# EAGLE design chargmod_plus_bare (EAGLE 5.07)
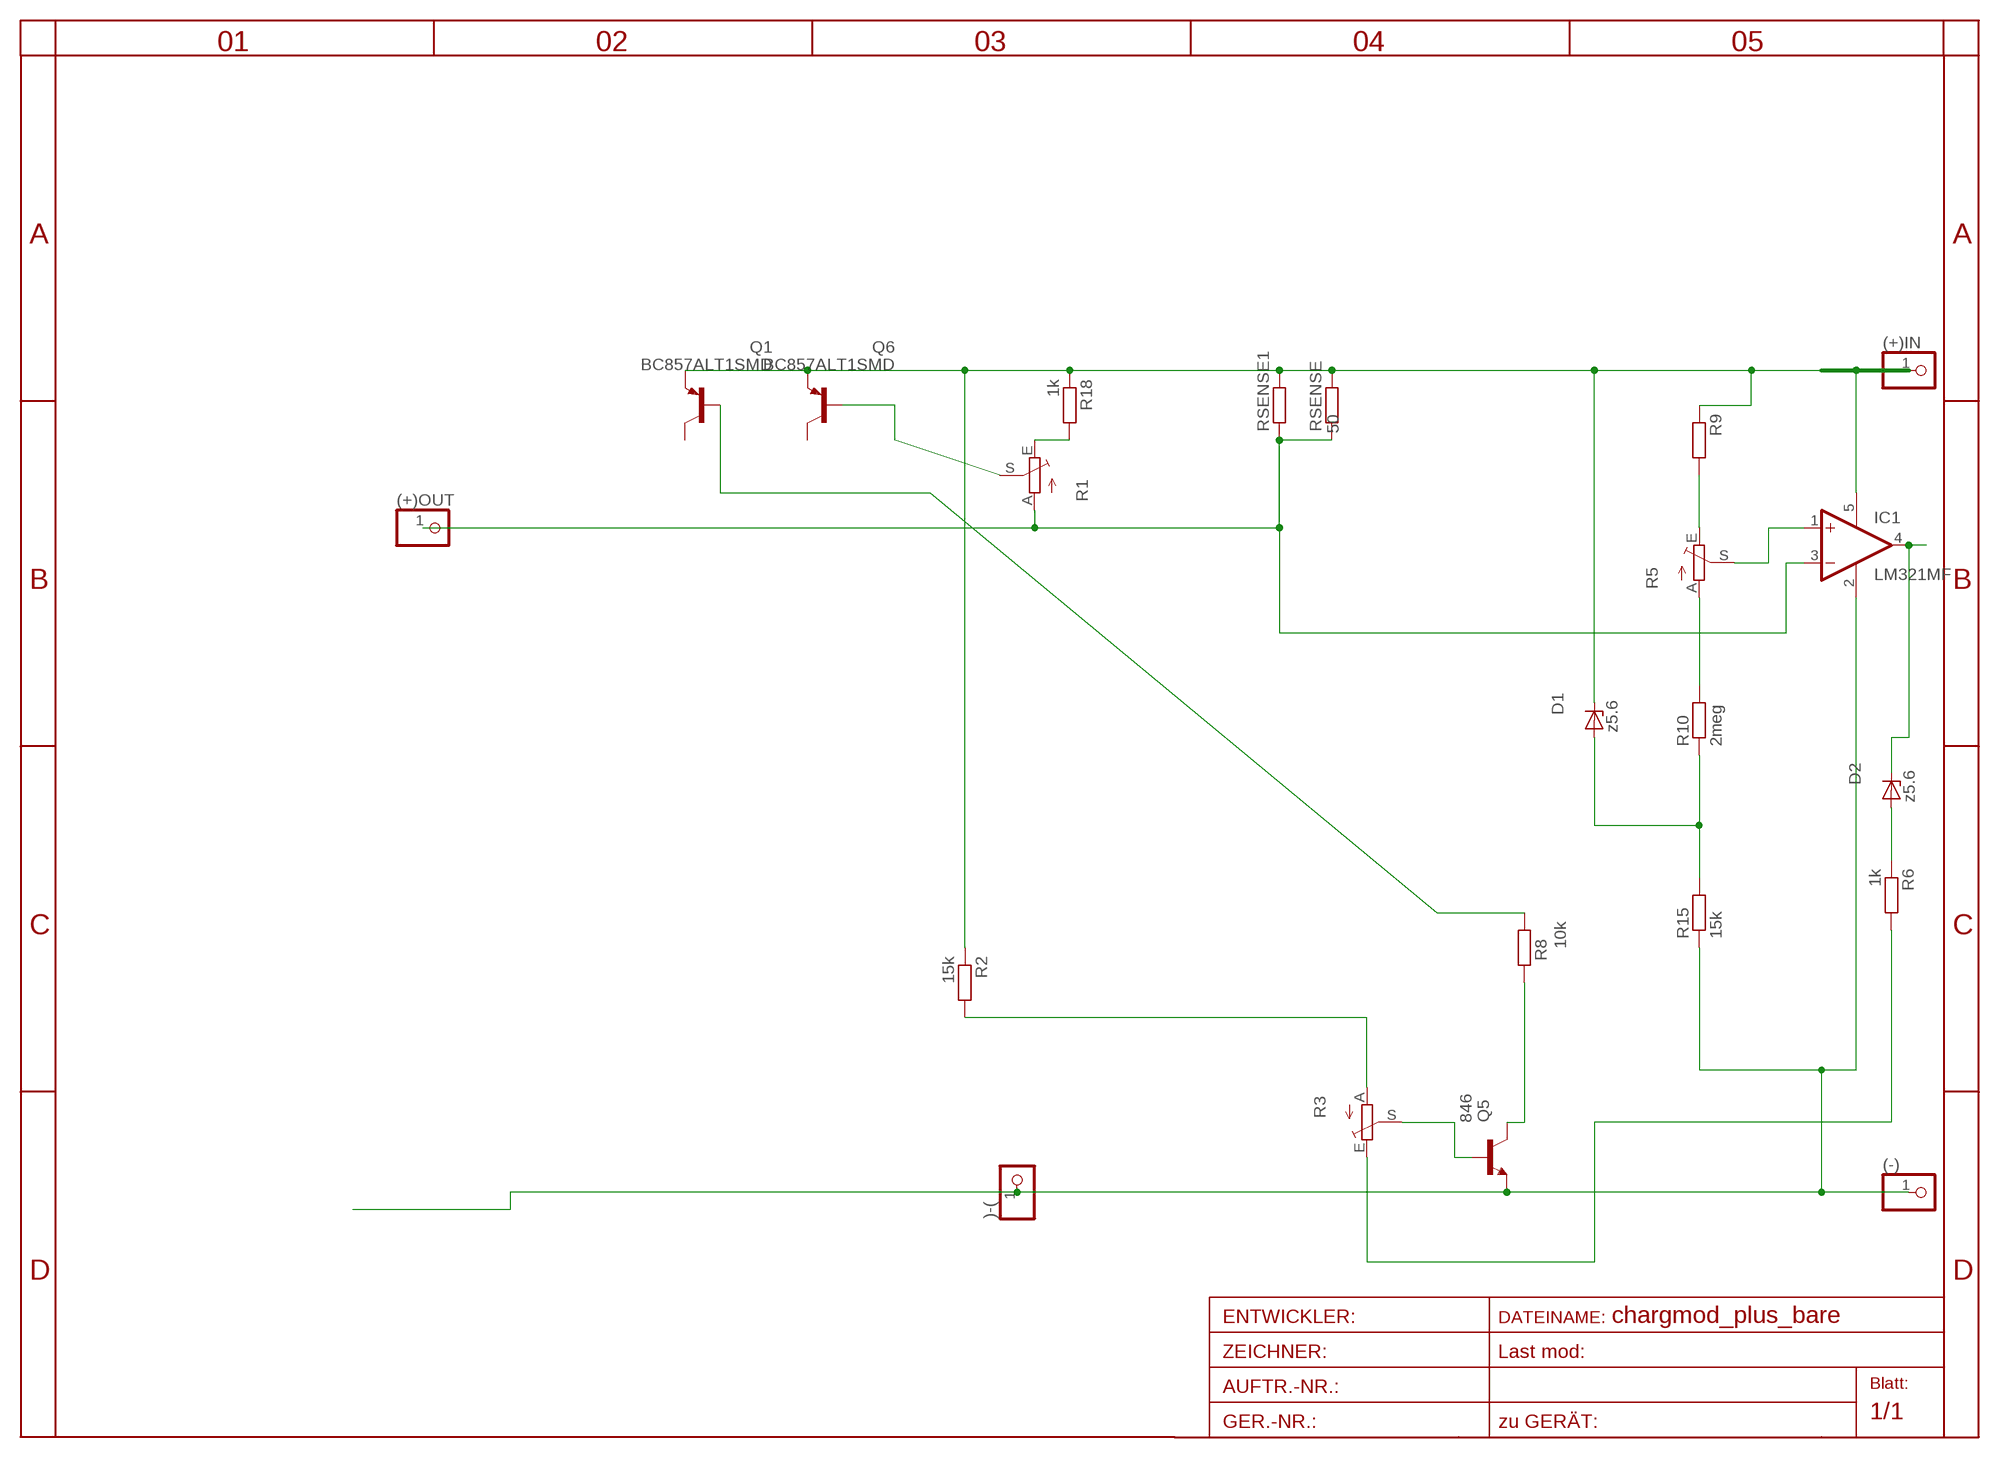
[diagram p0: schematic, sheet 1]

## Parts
(+)IN  PINHD-1X11MM6  [1X1MM8]
(+)OUT  PINHD-1X11MM6  [1X1MM8]
(-)  PINHD-1X11MM6  [1X1MM8]
)-(  PINHD-1X11MM6  [1X1MM8]
D1  z5.6  ZENER-DIODESOD80C  [SOD80C]
D2  z5.6  ZENER-DIODESOD80C  [SOD80C]
IC1  LM321MF  [SOT23-5]
Q1  BC857ALT1SMD  [SOT23-BEC]
Q5  846  BC846BSMD  [SOT23]
Q6  BC857ALT1SMD  [SOT23-BEC]
R1  TRIM_EU-S64W  [S64W]
R2  15k  R-EU_R0805  [R0805]
R3  TRIM_EU-S64W  [S64W]
R5  TRIM_EU-S64W  [S64W]
R6  1k  R-EU_R1206  [R1206]
R8  10k  R-EU_R0805  [R0805]
R9  50  R-EU_R0805  [R0805]
R10  2meg  R-EU_R0805  [R0805]
R15  15k  R-EU_R0805  [R0805]
R18  1k  R-EU_R1206  [R1206]
RSENSE  R-EU_0207/10  [0207/10]
RSENSE1  R-EU_0207/10  [0207/10]

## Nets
N$2: Q5.1(B) R3.S
N$3: R3.E R6.2
N$4: R2.2 R3.A
N$6: R5.A R10.2
N$7: Q1.B R8.1
N$9: (+)OUT.1 IC1.3(-IN) R1.A RSENSE1.1 RSENSE.1
N$13: D2.C IC1.4(OUT)
N$16: IC1.1(+IN) R5.S
N$17: Q6.B R1.S
N$19: D1.A R10.1 R15.2
N$20: Q5.3(C) R8.2
N$21: R5.E R9.2
N$22: R1.E R18.2
N$23: D2.A R6.1
V+IN: (+)IN.1 D1.C IC1.5(V+) Q1.E Q6.E R2.1 R9.1 R18.1 RSENSE1.2 RSENSE.2
VSS: (-).1 )-(.1 IC1.2(V-) Q5.2(E) R15.1
Unconnected: Q1.C Q6.C

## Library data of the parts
(+)IN (+)OUT (-) )-( = pinhead:PINHD-1X1: PIN HEADER
D1 D2 = diode-1:ZENER-DIODE: Z-Diode
IC1 = linear:LM321?*: Low Power Single Op Amp Source: http://cache.national.com/ds/LM/LM321.pdf
Q1 Q6 = transistor-pnp:BC857*: PNP Transistror
Q5 = transistor-npn:BC846*: NPN Transistor
R1 R3 R5 = pot:TRIM_EU-: POTENTIOMETER
R2 R6 R8-R10 R15 R18 RSENSE RSENSE1 = rcl:R-EU_: RESISTOR, European symbol

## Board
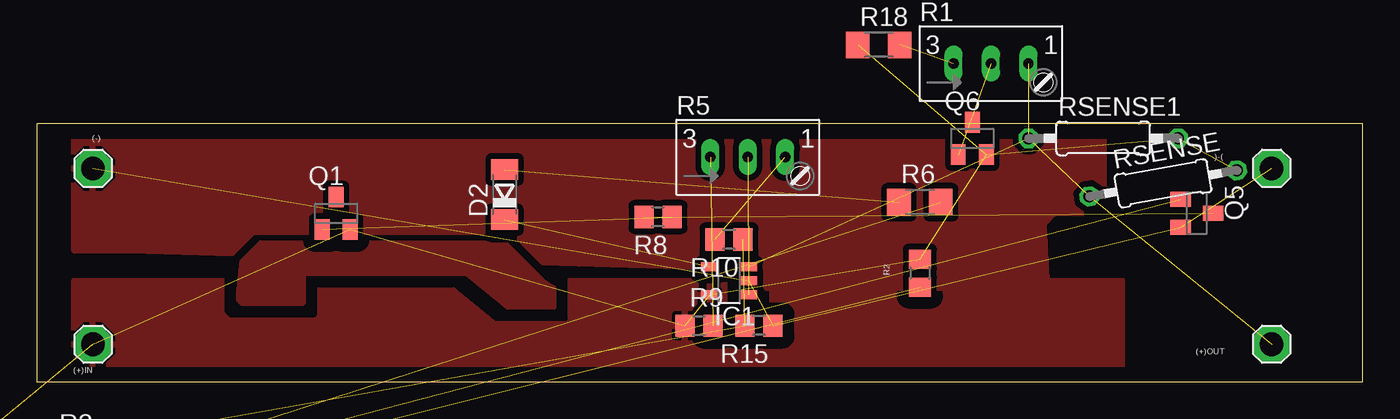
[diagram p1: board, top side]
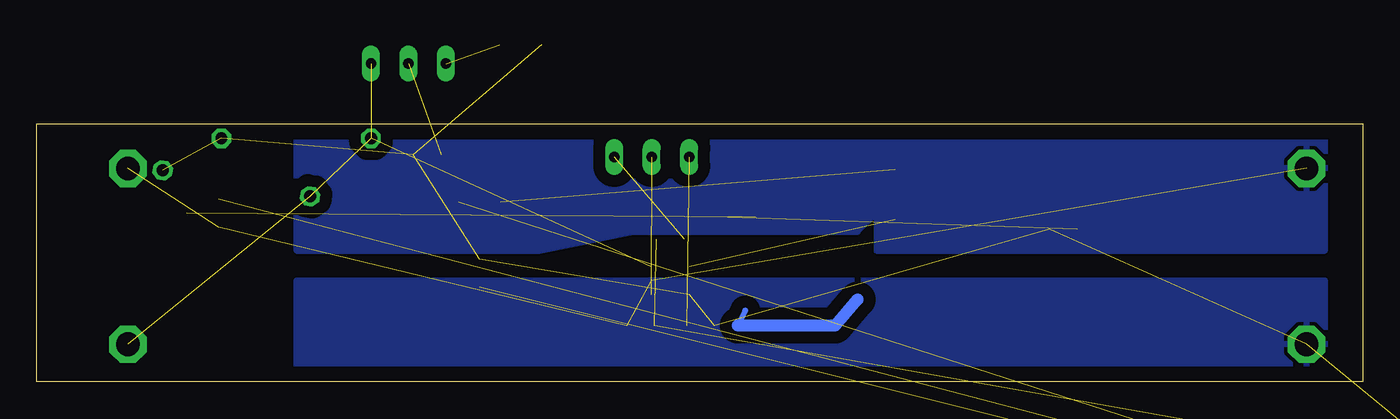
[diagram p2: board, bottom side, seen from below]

Size 90 x 17.5 mm. Coordinates in mm from the lower left corner, seen from the top.
Outline: 0,0 90,0 90,17.5 0,17.5 0,0
Copper layers (1*16): Top 0.035mm / dielectric 1.5mm / Bottom 0.035mm
Design rules "default *": minimum track width 10mil, minimum drill 14mil, track to track 8mil, track to pad 8mil, pad to pad 8mil, via to via 8mil, smd to smd 8mil, copper to edge 40mil, drill to drill 8mil, minimum pad ring 10mil, minimum via ring 8mil, stop-mask expansion 4mil, vias tented up to drill 0mil, thermal gap 10mil

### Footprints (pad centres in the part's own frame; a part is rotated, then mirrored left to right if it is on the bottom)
1X1MM8 = drill 1.6 pad 2.54 octagon: 1 0,0
SOD80C = smd 1.4 x 1.8: A 1.7,0; C -1.7,0
SOT23-5 = smd 0.6 x 1.2: 1 -0.95,-1.306; 2 0,-1.306; 3 0.95,-1.306; 4 0.95,1.306; 5 -0.95,1.306
SOT23-BEC = smd 1 x 1.4: B -0.95,-1.1; C 0,1.1; E 0.95,-1.1
SOT23 = smd 1 x 1.4: 1 -0.95,-1.1; 2 0.95,-1.1; 3 0,1.1
S64W = drill 0.7 long: A 2.54,1.27; E -2.54,1.27; S 0,1.27
R0805 = smd 1.3 x 1.5: 1 -0.95,0; 2 0.95,0
R1206 = smd 1.6 x 1.803: 1 -1.422,0; 2 1.422,0
0207/10 = drill 0.813 octagon: 1 -5.08,0; 2 5.08,0

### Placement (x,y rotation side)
(+)IN  3.81,2.54 0 top
(+)OUT  83.82,2.54 0 top
(-)  3.81,14.48 0 top
)-(  83.82,14.48 0 top
D1  not placed on the board
D2  31.75,12.7 90 top
IC1  46.99,6.86 90 top
Q1  20.32,11.43 0 top
Q5  78.74,11.43 270 top
Q6  63.5,16.51 0 top
R1  not placed on the board
R2  59.94,7.37 270 top
R3  not placed on the board
R5  48.26,13.97 0 top
R6  59.94,12.19 0 top
R8  42.16,11.18 180 top
R9  44.96,3.81 0 top
R10  46.99,9.65 180 top
R15  49.02,3.81 180 top
R18  not placed on the board
RSENSE  76.45,13.46 10 top
RSENSE1  72.39,16.51 0 top

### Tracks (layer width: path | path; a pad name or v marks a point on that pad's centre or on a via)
N$2  (1 unrouted)
N$3  (1 unrouted)
N$4  (1 unrouted)
N$6  (1 unrouted)
N$7  (1 unrouted)
N$9  (4 unrouted)
N$13  (1 unrouted)
N$16  (1 unrouted)
N$17  (1 unrouted)
N$19  (2 unrouted)
N$20  (1 unrouted)
N$21  (1 unrouted)
N$22  (1 unrouted)
N$23  (1 unrouted)
V+IN  (9 unrouted)
  pour Top (isolate 0.813, rank 5): 2.54,6.86 73.66,6.86 73.66,0.51 2.54,0.51
  pour Top: 73.66,5.59 73.66,3.05 69.85,3.05 69.85,4.32 71.12,5.59
  pour Bottom (isolate 0.813, rank 5): 2.54,6.86 72.39,6.86 72.39,0.51 2.54,0.51
VDD
  Bottom 0.406: 42.42,3.81 41.91,4.83
  Bottom 0.813: 42.42,3.81 35.81,3.81 34.29,5.59
  pour Top (isolate 0.813): 13.97,8.13 15.24,9.4 31.75,9.4 34.29,6.86 35.05,6.35 35.05,5.08 32,5.08 29.21,7.37 18.03,7.37 18.03,5.33 13.97,5.33 13.72,5.59
VSS  (4 unrouted)
  pour Top (isolate 0.406, rank 5): 6.35,8.89 2.54,8.89 2.54,16.51 72.39,16.51 72.39,11.43 69.09,11.43 68.33,10.67 68.58,6.35 49.53,6.35 49.53,7.62
  pour Bottom (isolate 0.813, rank 5): 33.02,8.89 2.54,8.89 2.54,16.51 72.39,16.51 72.39,8.89 55.88,8.89 49.53,10.16 34.29,10.16 33.02,11.43

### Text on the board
tTest: 500u | 5u | 2m | 5m | 2m | 500u | 1m | 500u | 5m
Document: vin-10/2m | Vin*1k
